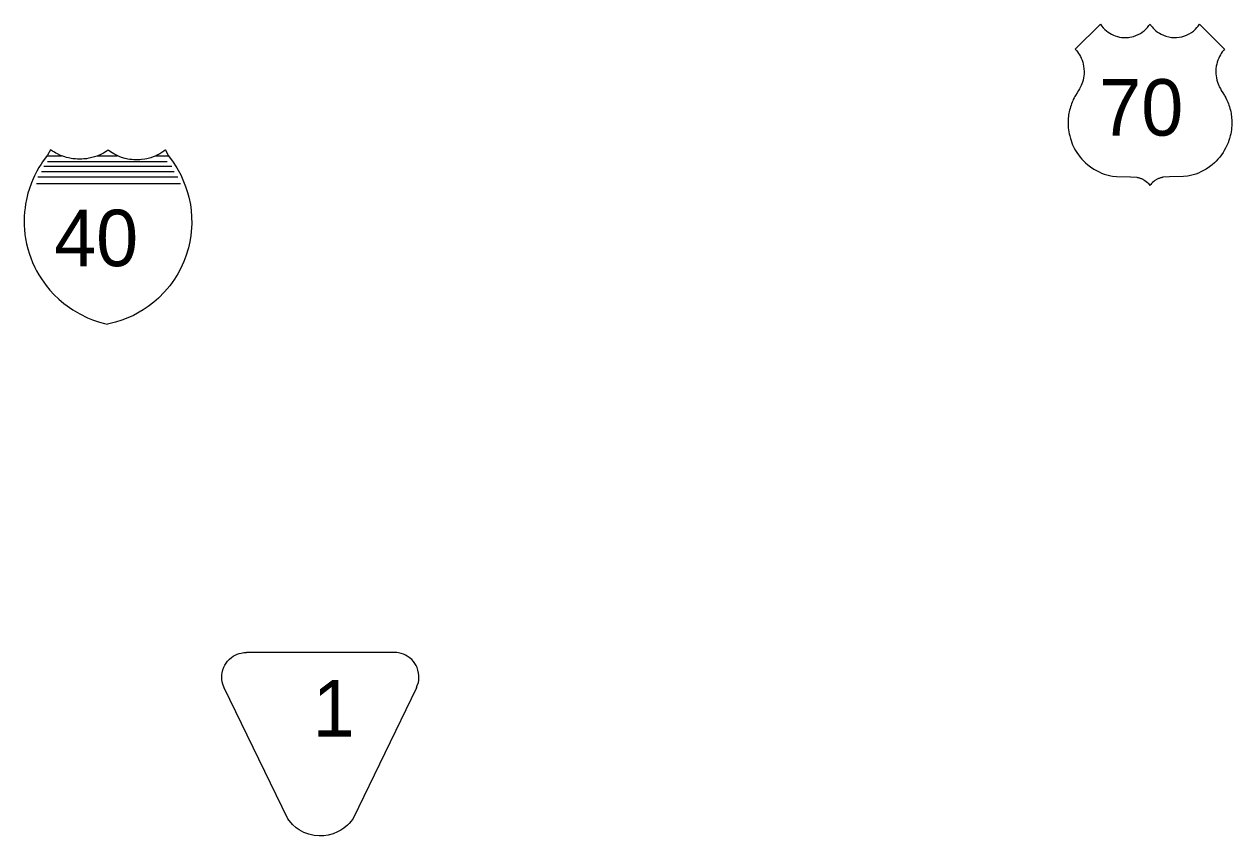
# Model space of a CAD drawing. Extents: x 1612280 to 1883141, y 560852 to 780851.
# Drawn here: x 1745088 to 1754117, y 658557 to 664628 of the extents above; entities that cross this region are included whole.
import ezdxf

# ---------------------------------------------------------------- set-up
doc = ezdxf.new("R2010")
doc.units = 0
for name, color, linetype in [('DESIGN - ROW - Easement Linework and Patterning', 7, 'Continuous'), ('SURVEY - DRAINAGE - Bridge Deck with Text', 7, 'Continuous'), ('SURVEY - DRAINAGE - Bridge Hydraulic Data with Text', 7, 'Continuous')]:
    doc.layers.add(name, color=color, linetype=linetype)

msp = doc.modelspace()

# ---------------------------------------------------------------- linework, layer by layer
at = {"layer": 'DESIGN - ROW - Easement Linework and Patterning'}
for points in [[(1747058.8, 658683.4), (1746584.3, 659663.9), (1746573.8, 659690.9), (1746569.3, 659708.9), (1746566.7, 659726.8), (1746565.9, 659742.4), (1746566.5, 659760.2), (1746568.7, 659776.7), (1746574.4, 659799.9), (1746581, 659817.5), (1746588.8, 659833.6), (1746598.9, 659849.8), (1746609.2, 659863.3), (1746624.6, 659879.5), (1746638.9, 659891.5), (1746652.1, 659900.7), (1746664.8, 659908), (1746681.3, 659915.7), (1746696.9, 659921.2), (1746709.7, 659924.6), (1746731.3, 659928.2), (1746750.7, 659929.2)], [(1747058.8, 658683.4), (1746584.3, 659663.9), (1746573.8, 659690.9), (1746569.3, 659708.9), (1746566.7, 659726.8), (1746565.9, 659742.4), (1746566.5, 659760.2), (1746568.7, 659776.7), (1746574.4, 659799.9), (1746581, 659817.5), (1746588.8, 659833.6), (1746598.9, 659849.8), (1746609.2, 659863.3), (1746624.6, 659879.5), (1746638.9, 659891.5), (1746652.1, 659900.7), (1746664.8, 659908), (1746681.3, 659915.7), (1746696.9, 659921.2), (1746709.7, 659924.6), (1746731.3, 659928.2), (1746750.7, 659929.2)], [(1748021.4, 659663.9), (1748027.5, 659681.6), (1748035.5, 659704.8), (1748038.4, 659721.4), (1748039.8, 659741.8), (1748039.4, 659757.1), (1748037.3, 659775), (1748032.1, 659797.4), (1748025.5, 659815.6), (1748018.7, 659830.2), (1748010, 659845), (1747998.4, 659861), (1747985.8, 659875), (1747967.1, 659891.3), (1747952.2, 659901.6), (1747938.3, 659909.4), (1747924, 659915.8), (1747907.7, 659921.5), (1747888, 659926.2), (1747874.1, 659928.2), (1747855, 659929.2), (1746750.7, 659929.2)], [(1748021.4, 659663.9), (1748027.5, 659681.6), (1748035.5, 659704.8), (1748038.4, 659721.4), (1748039.8, 659741.8), (1748039.4, 659757.1), (1748037.3, 659775), (1748032.1, 659797.4), (1748025.5, 659815.6), (1748018.7, 659830.2), (1748010, 659845), (1747998.4, 659861), (1747985.8, 659875), (1747967.1, 659891.3), (1747952.2, 659901.6), (1747938.3, 659909.4), (1747924, 659915.8), (1747907.7, 659921.5), (1747888, 659926.2), (1747874.1, 659928.2), (1747855, 659929.2), (1746750.7, 659929.2)], [(1748021.4, 659663.9), (1747548.3, 658686.3), (1747533.1, 658666), (1747518.7, 658649.7), (1747505.4, 658636.6), (1747477.3, 658613.5), (1747455.2, 658598.9), (1747431.2, 658586.1), (1747398.4, 658572.7), (1747360.7, 658562.6), (1747329, 658558.1), (1747294, 658557), (1747256.7, 658560.4), (1747216.2, 658569.7), (1747180.4, 658583.1), (1747144.8, 658602.1), (1747122.8, 658617.1), (1747093.4, 658642.6), (1747058.8, 658683.4)], [(1748021.4, 659663.9), (1747548.3, 658686.3), (1747533.1, 658666), (1747518.7, 658649.7), (1747505.4, 658636.6), (1747477.3, 658613.5), (1747455.2, 658598.9), (1747431.2, 658586.1), (1747398.4, 658572.7), (1747360.7, 658562.6), (1747329, 658558.1), (1747294, 658557), (1747256.7, 658560.4), (1747216.2, 658569.7), (1747180.4, 658583.1), (1747144.8, 658602.1), (1747122.8, 658617.1), (1747093.4, 658642.6), (1747058.8, 658683.4)]]:
    msp.add_lwpolyline(points, dxfattribs=at)
at = {"layer": 'SURVEY - DRAINAGE - Bridge Deck with Text'}
for points in [[(1752946.8, 664441.6), (1753134.2, 664628), (1753144, 664614.3), (1753156.3, 664599.5), (1753168.4, 664587.3), (1753179.6, 664577.5), (1753191.9, 664568.1), (1753204.8, 664559.7), (1753217.2, 664552.7), (1753231.7, 664545.8), (1753244.8, 664540.6), (1753261.2, 664535.4), (1753276.8, 664531.7), (1753293.3, 664529.1), (1753311, 664527.7), (1753319, 664527.5), (1753327.1, 664527.6), (1753335, 664528), (1753345.1, 664528.9), (1753355.5, 664530.4), (1753369, 664533), (1753381.5, 664536.2), (1753399.6, 664542.4), (1753416.9, 664549.9), (1753433.4, 664558.8), (1753447.3, 664567.8), (1753461, 664578.3), (1753474.3, 664590.2), (1753486.3, 664602.9), (1753497.5, 664616.8), (1753505.4, 664628), (1753512.3, 664618.1), (1753521, 664606.9), (1753529, 664597.9), (1753538.3, 664588.5), (1753550, 664578.1), (1753562.4, 664568.6), (1753575.5, 664560), (1753589.2, 664552.3), (1753605.1, 664544.8), (1753623.8, 664537.9), (1753645, 664532.3), (1753665.9, 664528.9), (1753684, 664527.6), (1753703.8, 664527.9), (1753724, 664530), (1753744.2, 664534), (1753766.5, 664540.8), (1753784.3, 664548.1), (1753798.8, 664555.5), (1753815.8, 664566.1), (1753830, 664576.6), (1753845.9, 664590.7), (1753856.6, 664601.9), (1753866.5, 664613.8), (1753876.5, 664628.1), (1754063.3, 664441.6)], [(1752946.8, 664441.6), (1753134.2, 664628), (1753144, 664614.3), (1753156.3, 664599.5), (1753168.4, 664587.3), (1753179.6, 664577.5), (1753191.9, 664568.1), (1753204.8, 664559.7), (1753217.2, 664552.7), (1753231.7, 664545.8), (1753244.8, 664540.6), (1753261.2, 664535.4), (1753276.8, 664531.7), (1753293.3, 664529.1), (1753311, 664527.7), (1753319, 664527.5), (1753327.1, 664527.6), (1753335, 664528), (1753345.1, 664528.9), (1753355.5, 664530.4), (1753369, 664533), (1753381.5, 664536.2), (1753399.6, 664542.4), (1753416.9, 664549.9), (1753433.4, 664558.8), (1753447.3, 664567.8), (1753461, 664578.3), (1753474.3, 664590.2), (1753486.3, 664602.9), (1753497.5, 664616.8), (1753505.4, 664628), (1753512.3, 664618.1), (1753521, 664606.9), (1753529, 664597.9), (1753538.3, 664588.5), (1753550, 664578.1), (1753562.4, 664568.6), (1753575.5, 664560), (1753589.2, 664552.3), (1753605.1, 664544.8), (1753623.8, 664537.9), (1753645, 664532.3), (1753665.9, 664528.9), (1753684, 664527.6), (1753703.8, 664527.9), (1753724, 664530), (1753744.2, 664534), (1753766.5, 664540.8), (1753784.3, 664548.1), (1753798.8, 664555.5), (1753815.8, 664566.1), (1753830, 664576.6), (1753845.9, 664590.7), (1753856.6, 664601.9), (1753866.5, 664613.8), (1753876.5, 664628.1), (1754063.3, 664441.6)], [(1752946.8, 664441.6), (1752955.9, 664430.9), (1752964.1, 664420.3), (1752971.7, 664409.1), (1752978, 664398.8), (1752984.8, 664386.4), (1752991.4, 664372.5), (1752997, 664358.4), (1753002.1, 664343), (1753005.9, 664328.6), (1753009.1, 664312.6), (1753011.4, 664294.9), (1753012.5, 664273.2), (1753012.1, 664256.8), (1753010.7, 664240.8), (1753008.6, 664226.8), (1753004.7, 664208.6), (1753000.8, 664194.8), (1752996.3, 664181.6), (1752991.4, 664169.5), (1752986.6, 664159.2), (1752978.8, 664145.4), (1752971.6, 664132.8), (1752961.1, 664115.2), (1752948.2, 664094.1), (1752944.5, 664088.1), (1752938.6, 664077.1), (1752932, 664063.9), (1752927.9, 664054.8), (1752923.1, 664043.5), (1752919, 664033.2), (1752915.1, 664022.2), (1752911.2, 664010.5), (1752907.5, 663997.9), (1752904, 663984.5), (1752901.5, 663973.3), (1752899.2, 663961.2), (1752897.2, 663949.3), (1752895.5, 663936.6), (1752894.3, 663925), (1752893.5, 663913.5), (1752893, 663902.6), (1752892.8, 663891.5), (1752893, 663879), (1752893.4, 663867.4), (1752894.5, 663852.9), (1752896.1, 663837.8), (1752898.4, 663822.5), (1752901.2, 663807.8), (1752904.8, 663791.5), (1752910.1, 663772.4), (1752914.8, 663757.8), (1752921.2, 663740.2), (1752927.2, 663726.6), (1752932.2, 663715), (1752939.5, 663700.4), (1752949.3, 663682.9), (1752958.4, 663668.2), (1752970.4, 663650.6), (1752983, 663634.3), (1752996.8, 663618), (1753011.3, 663602.7), (1753023.7, 663590.7), (1753040.6, 663576), (1753060.4, 663560.6), (1753084.6, 663544.3), (1753104.8, 663532.5), (1753124.3, 663522.6), (1753142.3, 663514.5), (1753163.1, 663506.5), (1753182.4, 663500.1), (1753201.7, 663494.8), (1753211.6, 663492.5), (1753224.3, 663490.8), (1753254.4, 663488.2), (1753360, 663484.9), (1753407.7, 663482.4), (1753412.2, 663481.9), (1753417, 663480.8), (1753422.1, 663479.5), (1753427.2, 663478), (1753431.9, 663476.5), (1753436.5, 663474.7), (1753441.9, 663472.6), (1753446.2, 663470.6), (1753451.4, 663468.1), (1753455.2, 663466.1), (1753459.3, 663463.8), (1753467.8, 663458.4), (1753476.9, 663451.7), (1753485.5, 663444.3), (1753493.1, 663436.8), (1753499.5, 663429.5), (1753505.1, 663421.2)], [(1752946.8, 664441.6), (1752955.9, 664430.9), (1752964.1, 664420.3), (1752971.7, 664409.1), (1752978, 664398.8), (1752984.8, 664386.4), (1752991.4, 664372.5), (1752997, 664358.4), (1753002.1, 664343), (1753005.9, 664328.6), (1753009.1, 664312.6), (1753011.4, 664294.9), (1753012.5, 664273.2), (1753012.1, 664256.8), (1753010.7, 664240.8), (1753008.6, 664226.8), (1753004.7, 664208.6), (1753000.8, 664194.8), (1752996.3, 664181.6), (1752991.4, 664169.5), (1752986.6, 664159.2), (1752978.8, 664145.4), (1752971.6, 664132.8), (1752961.1, 664115.2), (1752948.2, 664094.1), (1752944.5, 664088.1), (1752938.6, 664077.1), (1752932, 664063.9), (1752927.9, 664054.8), (1752923.1, 664043.5), (1752919, 664033.2), (1752915.1, 664022.2), (1752911.2, 664010.5), (1752907.5, 663997.9), (1752904, 663984.5), (1752901.5, 663973.3), (1752899.2, 663961.2), (1752897.2, 663949.3), (1752895.5, 663936.6), (1752894.3, 663925), (1752893.5, 663913.5), (1752893, 663902.6), (1752892.8, 663891.5), (1752893, 663879), (1752893.4, 663867.4), (1752894.5, 663852.9), (1752896.1, 663837.8), (1752898.4, 663822.5), (1752901.2, 663807.8), (1752904.8, 663791.5), (1752910.1, 663772.4), (1752914.8, 663757.8), (1752921.2, 663740.2), (1752927.2, 663726.6), (1752932.2, 663715), (1752939.5, 663700.4), (1752949.3, 663682.9), (1752958.4, 663668.2), (1752970.4, 663650.6), (1752983, 663634.3), (1752996.8, 663618), (1753011.3, 663602.7), (1753023.7, 663590.7), (1753040.6, 663576), (1753060.4, 663560.6), (1753084.6, 663544.3), (1753104.8, 663532.5), (1753124.3, 663522.6), (1753142.3, 663514.5), (1753163.1, 663506.5), (1753182.4, 663500.1), (1753201.7, 663494.8), (1753211.6, 663492.5), (1753224.3, 663490.8), (1753254.4, 663488.2), (1753360, 663484.9), (1753407.7, 663482.4), (1753412.2, 663481.9), (1753417, 663480.8), (1753422.1, 663479.5), (1753427.2, 663478), (1753431.9, 663476.5), (1753436.5, 663474.7), (1753441.9, 663472.6), (1753446.2, 663470.6), (1753451.4, 663468.1), (1753455.2, 663466.1), (1753459.3, 663463.8), (1753467.8, 663458.4), (1753476.9, 663451.7), (1753485.5, 663444.3), (1753493.1, 663436.8), (1753499.5, 663429.5), (1753505.1, 663421.2)], [(1754063.3, 664441.6), (1754054.2, 664431), (1754046, 664420.3), (1754038.4, 664409.1), (1754032.1, 664398.9), (1754025.3, 664386.4), (1754018.8, 664372.5), (1754013.1, 664358.5), (1754008, 664343.1), (1754004.2, 664328.6), (1754001, 664312.6), (1753998.7, 664294.9), (1753997.6, 664273.2), (1753998, 664256.8), (1753999.4, 664240.9), (1754001.5, 664226.9), (1754005.4, 664208.6), (1754009.3, 664194.8), (1754013.8, 664181.7), (1754018.8, 664169.6), (1754023.6, 664159.2), (1754031.3, 664145.5), (1754038.6, 664132.9), (1754049, 664115.2), (1754061.9, 664094.2), (1754065.6, 664088.2), (1754071.5, 664077.1), (1754078.1, 664064), (1754082.3, 664054.9), (1754087.1, 664043.6), (1754091.2, 664033.2), (1754095.1, 664022.3), (1754098.9, 664010.5), (1754102.6, 663997.9), (1754106.1, 663984.5), (1754108.6, 663973.3), (1754111, 663961.3), (1754112.9, 663949.4), (1754114.6, 663936.6), (1754115.8, 663925.1), (1754116.6, 663913.5), (1754117.1, 663902.6), (1754117.3, 663891.5), (1754117.2, 663879), (1754116.7, 663867.5), (1754115.7, 663852.9), (1754114, 663837.8), (1754111.7, 663822.5), (1754109, 663807.8), (1754105.3, 663791.5), (1754100, 663772.4), (1754095.4, 663757.9), (1754088.9, 663740.3), (1754083, 663726.6), (1754077.9, 663715), (1754070.6, 663700.4), (1754060.8, 663682.9), (1754051.7, 663668.2), (1754039.7, 663650.7), (1754027.2, 663634.3), (1754013.4, 663618.1), (1753998.9, 663602.7), (1753986.4, 663590.7), (1753969.5, 663576), (1753949.8, 663560.6), (1753925.6, 663544.4), (1753905.3, 663532.6), (1753885.9, 663522.6), (1753867.9, 663514.5), (1753847, 663506.5), (1753827.8, 663500.1), (1753808.4, 663494.8), (1753798.6, 663492.5), (1753785.9, 663490.9), (1753755.8, 663488.2), (1753650.2, 663484.9), (1753602.5, 663482.4), (1753598, 663481.9), (1753593.2, 663480.8), (1753588, 663479.5), (1753583, 663478), (1753578.3, 663476.5), (1753573.6, 663474.7), (1753568.3, 663472.6), (1753563.9, 663470.7), (1753558.8, 663468.1), (1753554.9, 663466.1), (1753550.9, 663463.8), (1753542.3, 663458.4), (1753533.2, 663451.7), (1753524.7, 663444.3), (1753517, 663436.8), (1753510.6, 663429.5), (1753505.1, 663421.2)], [(1754063.3, 664441.6), (1754054.2, 664431), (1754046, 664420.3), (1754038.4, 664409.1), (1754032.1, 664398.9), (1754025.3, 664386.4), (1754018.8, 664372.5), (1754013.1, 664358.5), (1754008, 664343.1), (1754004.2, 664328.6), (1754001, 664312.6), (1753998.7, 664294.9), (1753997.6, 664273.2), (1753998, 664256.8), (1753999.4, 664240.9), (1754001.5, 664226.9), (1754005.4, 664208.6), (1754009.3, 664194.8), (1754013.8, 664181.7), (1754018.8, 664169.6), (1754023.6, 664159.2), (1754031.3, 664145.5), (1754038.6, 664132.9), (1754049, 664115.2), (1754061.9, 664094.2), (1754065.6, 664088.2), (1754071.5, 664077.1), (1754078.1, 664064), (1754082.3, 664054.9), (1754087.1, 664043.6), (1754091.2, 664033.2), (1754095.1, 664022.3), (1754098.9, 664010.5), (1754102.6, 663997.9), (1754106.1, 663984.5), (1754108.6, 663973.3), (1754111, 663961.3), (1754112.9, 663949.4), (1754114.6, 663936.6), (1754115.8, 663925.1), (1754116.6, 663913.5), (1754117.1, 663902.6), (1754117.3, 663891.5), (1754117.2, 663879), (1754116.7, 663867.5), (1754115.7, 663852.9), (1754114, 663837.8), (1754111.7, 663822.5), (1754109, 663807.8), (1754105.3, 663791.5), (1754100, 663772.4), (1754095.4, 663757.9), (1754088.9, 663740.3), (1754083, 663726.6), (1754077.9, 663715), (1754070.6, 663700.4), (1754060.8, 663682.9), (1754051.7, 663668.2), (1754039.7, 663650.7), (1754027.2, 663634.3), (1754013.4, 663618.1), (1753998.9, 663602.7), (1753986.4, 663590.7), (1753969.5, 663576), (1753949.8, 663560.6), (1753925.6, 663544.4), (1753905.3, 663532.6), (1753885.9, 663522.6), (1753867.9, 663514.5), (1753847, 663506.5), (1753827.8, 663500.1), (1753808.4, 663494.8), (1753798.6, 663492.5), (1753785.9, 663490.9), (1753755.8, 663488.2), (1753650.2, 663484.9), (1753602.5, 663482.4), (1753598, 663481.9), (1753593.2, 663480.8), (1753588, 663479.5), (1753583, 663478), (1753578.3, 663476.5), (1753573.6, 663474.7), (1753568.3, 663472.6), (1753563.9, 663470.7), (1753558.8, 663468.1), (1753554.9, 663466.1), (1753550.9, 663463.8), (1753542.3, 663458.4), (1753533.2, 663451.7), (1753524.7, 663444.3), (1753517, 663436.8), (1753510.6, 663429.5), (1753505.1, 663421.2)]]:
    msp.add_lwpolyline(points, dxfattribs=at)
at = {"layer": 'SURVEY - DRAINAGE - Bridge Hydraulic Data with Text'}
for p, q in [((1745259.6, 663643), (1745366.2, 663643.1)), ((1745259.6, 663643), (1745366.2, 663643.1)), ((1745635.4, 663643.1), (1745782.7, 663643.1)), ((1745635.4, 663643.1), (1745782.7, 663643.1)), ((1746068.2, 663643.1), (1746168, 663643.1)), ((1746068.2, 663643.1), (1746168, 663643.1)), ((1745235.8, 663566), (1746191.7, 663566)), ((1745235.8, 663566), (1746191.7, 663566)), ((1745263.5, 663599.8), (1746157.7, 663599.9)), ((1745263.5, 663599.8), (1746157.7, 663599.9)), ((1745191.1, 663486.6), (1746236.4, 663486.7)), ((1745191.1, 663486.6), (1746236.4, 663486.7)), ((1745218.8, 663526.9), (1746210.9, 663527)), ((1745218.8, 663526.9), (1746210.9, 663527)), ((1745179.4, 663435.9), (1746256.7, 663435.9)), ((1745179.4, 663435.9), (1746256.7, 663435.9))]:
    msp.add_line(p, q, dxfattribs=at)
for points in [[(1745286.2, 663688.2), (1745263.6, 663649.3), (1745244.6, 663624.9), (1745225.1, 663597.6), (1745214.6, 663581.8), (1745199, 663556.8), (1745183.2, 663528.9), (1745165.2, 663493.5), (1745154.4, 663470), (1745142.6, 663441.6), (1745124.7, 663391.1), (1745116.7, 663363.8), (1745110.4, 663339.8), (1745104.9, 663315.6), (1745098.7, 663282.5), (1745094.7, 663255.3), (1745091.3, 663223.5), (1745089.1, 663190.4), (1745088.2, 663151.2), (1745088.9, 663122.4), (1745090.7, 663092.2), (1745094.4, 663055.5), (1745099, 663024.7), (1745106.7, 662984.8), (1745116.2, 662946.3), (1745127.7, 662908.1), (1745137.9, 662879), (1745151.1, 662846), (1745167.9, 662809.1), (1745181.4, 662782.7), (1745197.8, 662753.6), (1745217.4, 662722.3), (1745253.2, 662672.1), (1745280, 662639.4), (1745310.9, 662605.7), (1745347.1, 662570.8), (1745384.5, 662539), (1745451.8, 662491), (1745503.5, 662460.7), (1745562.5, 662432.2), (1745598.6, 662417.6), (1745651.8, 662399.8), (1745688.6, 662389.9), (1745711.5, 662384.2)], [(1745286.2, 663688.2), (1745263.6, 663649.3), (1745244.6, 663624.9), (1745225.1, 663597.6), (1745214.6, 663581.8), (1745199, 663556.8), (1745183.2, 663528.9), (1745165.2, 663493.5), (1745154.4, 663470), (1745142.6, 663441.6), (1745124.7, 663391.1), (1745116.7, 663363.8), (1745110.4, 663339.8), (1745104.9, 663315.6), (1745098.7, 663282.5), (1745094.7, 663255.3), (1745091.3, 663223.5), (1745089.1, 663190.4), (1745088.2, 663151.2), (1745088.9, 663122.4), (1745090.7, 663092.2), (1745094.4, 663055.5), (1745099, 663024.7), (1745106.7, 662984.8), (1745116.2, 662946.3), (1745127.7, 662908.1), (1745137.9, 662879), (1745151.1, 662846), (1745167.9, 662809.1), (1745181.4, 662782.7), (1745197.8, 662753.6), (1745217.4, 662722.3), (1745253.2, 662672.1), (1745280, 662639.4), (1745310.9, 662605.7), (1745347.1, 662570.8), (1745384.5, 662539), (1745451.8, 662491), (1745503.5, 662460.7), (1745562.5, 662432.2), (1745598.6, 662417.6), (1745651.8, 662399.8), (1745688.6, 662389.9), (1745711.5, 662384.2)], [(1746144.6, 663686.9), (1746132.1, 663677.7), (1746117.6, 663667.8), (1746102.6, 663658.8), (1746086.6, 663650.2), (1746074.2, 663644.3), (1746052.4, 663635.2), (1746034.5, 663629), (1746005.8, 663621.3), (1745990.6, 663618.2), (1745966.2, 663614.8), (1745953.4, 663613.6), (1745937.3, 663612.9), (1745917.1, 663613), (1745908.5, 663613.4), (1745894.5, 663614.5), (1745877.5, 663616.6), (1745864.5, 663618.8), (1745843.8, 663623.4), (1745816.1, 663631.5), (1745798, 663638.3), (1745782.7, 663644.9), (1745758.5, 663657.2), (1745734.3, 663672), (1745715.4, 663685.7), (1745700.5, 663675.7), (1745681, 663664.1), (1745660.6, 663653.7), (1745645, 663646.8), (1745630.6, 663641.1), (1745614.3, 663635.5), (1745595.2, 663630), (1745583.1, 663627.1), (1745572.6, 663624.9), (1745553.5, 663621.8), (1745534.1, 663619.6), (1745520.2, 663618.7), (1745506.3, 663618.3), (1745488.1, 663618.5), (1745471, 663619.6), (1745451.8, 663621.8), (1745438.8, 663623.8), (1745419.7, 663627.7), (1745404.6, 663631.5), (1745392.9, 663634.9), (1745377.9, 663639.9), (1745366.3, 663644.3), (1745355.3, 663648.9), (1745338, 663656.9), (1745325.8, 663663.3), (1745314.6, 663669.6), (1745299.3, 663679.2), (1745286.2, 663688.2)], [(1746144.6, 663686.9), (1746132.1, 663677.7), (1746117.6, 663667.8), (1746102.6, 663658.8), (1746086.6, 663650.2), (1746074.2, 663644.3), (1746052.4, 663635.2), (1746034.5, 663629), (1746005.8, 663621.3), (1745990.6, 663618.2), (1745966.2, 663614.8), (1745953.4, 663613.6), (1745937.3, 663612.9), (1745917.1, 663613), (1745908.5, 663613.4), (1745894.5, 663614.5), (1745877.5, 663616.6), (1745864.5, 663618.8), (1745843.8, 663623.4), (1745816.1, 663631.5), (1745798, 663638.3), (1745782.7, 663644.9), (1745758.5, 663657.2), (1745734.3, 663672), (1745715.4, 663685.7), (1745700.5, 663675.7), (1745681, 663664.1), (1745660.6, 663653.7), (1745645, 663646.8), (1745630.6, 663641.1), (1745614.3, 663635.5), (1745595.2, 663630), (1745583.1, 663627.1), (1745572.6, 663624.9), (1745553.5, 663621.8), (1745534.1, 663619.6), (1745520.2, 663618.7), (1745506.3, 663618.3), (1745488.1, 663618.5), (1745471, 663619.6), (1745451.8, 663621.8), (1745438.8, 663623.8), (1745419.7, 663627.7), (1745404.6, 663631.5), (1745392.9, 663634.9), (1745377.9, 663639.9), (1745366.3, 663644.3), (1745355.3, 663648.9), (1745338, 663656.9), (1745325.8, 663663.3), (1745314.6, 663669.6), (1745299.3, 663679.2), (1745286.2, 663688.2)], [(1746144.6, 663686.9), (1746164.4, 663646.1), (1746197.5, 663602.6), (1746229.6, 663553.4), (1746258.4, 663501), (1746275.4, 663464.7), (1746295.6, 663413.8), (1746310, 663369.3), (1746319.3, 663334.5), (1746330.7, 663278.3), (1746336.7, 663233.7), (1746340.3, 663186), (1746340.9, 663134), (1746334.2, 663047.2), (1746326.2, 662999.2), (1746315.8, 662953.8), (1746297.1, 662892.5), (1746282.1, 662853), (1746256.8, 662798), (1746236.4, 662760.2), (1746212.1, 662720.9), (1746176.4, 662671.1), (1746138, 662625.4), (1746091.7, 662578.5), (1746057.7, 662548.7), (1746014.8, 662515.6), (1745978, 662490.8), (1745905.5, 662450), (1745863.2, 662430.7), (1745819.1, 662413.7), (1745770.6, 662398.3), (1745711.5, 662384.2)], [(1746144.6, 663686.9), (1746164.4, 663646.1), (1746197.5, 663602.6), (1746229.6, 663553.4), (1746258.4, 663501), (1746275.4, 663464.7), (1746295.6, 663413.8), (1746310, 663369.3), (1746319.3, 663334.5), (1746330.7, 663278.3), (1746336.7, 663233.7), (1746340.3, 663186), (1746340.9, 663134), (1746334.2, 663047.2), (1746326.2, 662999.2), (1746315.8, 662953.8), (1746297.1, 662892.5), (1746282.1, 662853), (1746256.8, 662798), (1746236.4, 662760.2), (1746212.1, 662720.9), (1746176.4, 662671.1), (1746138, 662625.4), (1746091.7, 662578.5), (1746057.7, 662548.7), (1746014.8, 662515.6), (1745978, 662490.8), (1745905.5, 662450), (1745863.2, 662430.7), (1745819.1, 662413.7), (1745770.6, 662398.3), (1745711.5, 662384.2)]]:
    msp.add_lwpolyline(points, dxfattribs=at)

# ---------------------------------------------------------------- texts
at = {"layer": 'DESIGN - ROW - Easement Linework and Patterning'}
msp.add_text('1', height=422.4, rotation=0.00116, dxfattribs=at).set_placement((1747245.4, 659299.6))
msp.add_text('1', height=422.4, rotation=0.00116, dxfattribs=at).set_placement((1747245.4, 659299.6))
at = {"layer": 'SURVEY - DRAINAGE - Bridge Deck with Text'}
msp.add_text('70', height=422.4, rotation=0.00128, dxfattribs=at).set_placement((1753126, 663794.2))
msp.add_text('70', height=422.4, rotation=0.00128, dxfattribs=at).set_placement((1753126, 663794.2))
at = {"layer": 'SURVEY - DRAINAGE - Bridge Hydraulic Data with Text'}
msp.add_text('40', height=422.4, rotation=0.00129, dxfattribs=at).set_placement((1745312.4, 662817.8))
msp.add_text('40', height=422.4, rotation=0.00129, dxfattribs=at).set_placement((1745312.4, 662817.8))

doc.saveas('drawing.dxf')
